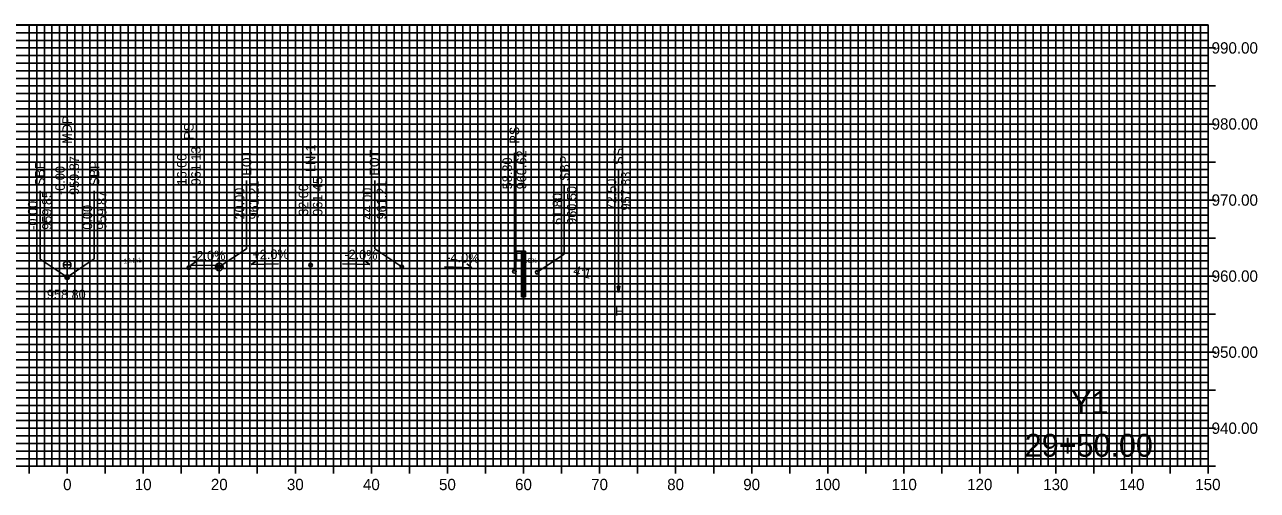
# Model space of a CAD drawing. Extents: x -157 to 156, y 932 to 993.
# Drawn here: x -5.6 to 156.5, y 931.8 to 993.1 of the extents above; entities that cross this region are included whole.
import ezdxf

# ---------------------------------------------------------------- set-up
doc = ezdxf.new("R2010")
doc.units = 0
for name, color, linetype in [('E_NCDOT_Terrain_Model_Boundary', 7, 'Continuous'), ('E_NCDOT_Terrain_Model_Breakline', 7, 'Continuous'), ('E_NCDOT_Terrain_Model_Contour_Imported', 7, 'Continuous'), ('E_NCDOT_Terrain_Model_Contour_Minor', 7, 'Continuous'), ('E_NCDOT_Terrain_Model_Flow_Arrows', 7, 'Continuous'), ('E_NCDOT_Terrain_Model_Hole', 7, 'Continuous'), ('E_NCDOT_Terrain_Model_Island', 7, 'Continuous'), ('E_NCDOT_Terrain_Model_Points_High', 7, 'Continuous'), ('E_NCDOT_Terrain_Model_Points_Low', 7, 'Continuous'), ('E_NCDOT_Terrain_Model_Spot_Elevation', 7, 'Continuous'), ('E_NCDOT_Terrain_Model_Triangles', 7, 'Continuous'), ('E_NCDOT_Terrain_Model_Void', 7, 'Continuous'), ('E_NCDOT_Vertical_Profile_Ground_Line', 7, 'Continuous'), ('P_HYD_Contour_Major', 7, 'Continuous'), ('P_HYD_Contour_Minor', 7, 'Continuous'), ('P_HYD_TC_Ditch_UCE', 7, 'Continuous'), ('P_HYD_TL_Ditch_Boundary', 7, 'Continuous')]:
    doc.layers.add(name, color=color, linetype=linetype)

msp = doc.modelspace()

# ---------------------------------------------------------------- linework, layer by layer
at = {"layer": 'E_NCDOT_Terrain_Model_Boundary'}
for p, q in [((16.2, 961.38), (16.88, 961.87)), ((19.8, 961.45), (16.2, 961.38)), ((24.2, 961.54), (24.88, 962.03)), ((27.8, 961.61), (24.2, 961.54)), ((36.2, 961.61), (39.8, 961.54)), ((39.8, 961.54), (39.12, 962.03)), ((49.6, 961.23), (53.2, 961.09)), ((53.2, 961.09), (52.53, 961.6))]:
    msp.add_line(p, q, dxfattribs=at)
at = {"layer": 'E_NCDOT_Terrain_Model_Breakline'}
for p, q in [((0, 935), (0, 993.06)), ((10, 935), (10, 993.06)), ((20, 935), (20, 993.06)), ((30, 935), (30, 993.06)), ((40, 935), (40, 993.06)), ((50, 935), (50, 993.06)), ((60, 935), (60, 993.06)), ((70, 935), (70, 993.06)), ((80, 935), (80, 993.06)), ((90, 935), (90, 993.06)), ((100, 935), (100, 993.06)), ((110, 935), (110, 993.06)), ((120, 935), (120, 993.06)), ((130, 935), (130, 993.06)), ((140, 935), (140, 993.06)), ((-150, 990), (150, 990)), ((-150, 980), (150, 980)), ((-150, 970), (150, 970)), ((-150, 960), (150, 960)), ((-150, 950), (150, 950)), ((-150, 940), (150, 940))]:
    msp.add_line(p, q, dxfattribs=at)
at = {"layer": 'E_NCDOT_Terrain_Model_Flow_Arrows'}
for p, q in [((-150, 993.06), (150, 993.06)), ((150, 935), (150, 993.06)), ((-150, 935), (150, 935))]:
    msp.add_line(p, q, dxfattribs=at)
at = {"layer": 'E_NCDOT_Terrain_Model_Island'}
for p, q in [((-0.5, 961.47), (0.5, 961.47)), ((0, 961.97), (0, 960.97)), ((19.5, 961.21), (20.5, 961.21)), ((19.5, 961.21), (20.5, 961.21)), ((20, 961.71), (20, 960.71)), ((20, 961.71), (20, 960.71))]:
    msp.add_line(p, q, dxfattribs=at)
for points in [[(-0.5, 961.47), (0, 961.47), (0, 961.97)], [(0.5, 961.47), (0, 961.47), (0, 960.97)], [(19.5, 961.21), (20, 961.21), (20, 961.71)], [(19.5, 961.21), (20, 961.21), (20, 961.71)], [(20.5, 961.21), (20, 961.21), (20, 960.71)], [(20.5, 961.21), (20, 961.21), (20, 960.71)]]:
    msp.add_lwpolyline(points, dxfattribs=at)
for centre in [(0, 961.47), (20, 961.21), (20, 961.21)]:
    msp.add_circle(centre, 0.5, dxfattribs=at)
for centre, start, end in [((0, 961.47), 90, 180), ((0, 961.47), 270, 0), ((20, 961.21), 90, 180), ((20, 961.21), 90, 180), ((20, 961.21), 270, 0), ((20, 961.21), 270, 0)]:
    msp.add_arc(centre, 0.5, start, end, dxfattribs=at)
at = {"layer": 'E_NCDOT_Terrain_Model_Points_High'}
for p, q in [((-150, 993), (150, 993)), ((-150, 992), (150, 992)), ((-4, 935), (-4, 993.06)), ((-3, 935), (-3, 993.06)), ((-2, 935), (-2, 993.06)), ((-1, 935), (-1, 993.06)), ((1, 935), (1, 993.06)), ((2, 935), (2, 993.06)), ((3, 935), (3, 993.06)), ((4, 935), (4, 993.06)), ((6, 935), (6, 993.06)), ((7, 935), (7, 993.06)), ((8, 935), (8, 993.06)), ((9, 935), (9, 993.06)), ((11, 935), (11, 993.06)), ((12, 935), (12, 993.06)), ((13, 935), (13, 993.06)), ((14, 935), (14, 993.06)), ((16, 935), (16, 993.06)), ((17, 935), (17, 993.06)), ((18, 935), (18, 993.06)), ((19, 935), (19, 993.06)), ((21, 935), (21, 993.06)), ((22, 935), (22, 993.06)), ((23, 935), (23, 993.06)), ((24, 935), (24, 993.06)), ((26, 935), (26, 993.06)), ((27, 935), (27, 993.06)), ((28, 935), (28, 993.06)), ((29, 935), (29, 993.06)), ((31, 935), (31, 993.06)), ((32, 935), (32, 993.06)), ((33, 935), (33, 993.06)), ((34, 935), (34, 993.06)), ((36, 935), (36, 993.06)), ((37, 935), (37, 993.06)), ((38, 935), (38, 993.06)), ((39, 935), (39, 993.06)), ((41, 935), (41, 993.06)), ((42, 935), (42, 993.06)), ((43, 935), (43, 993.06)), ((44, 935), (44, 993.06)), ((46, 935), (46, 993.06)), ((47, 935), (47, 993.06)), ((48, 935), (48, 993.06)), ((49, 935), (49, 993.06)), ((51, 935), (51, 993.06)), ((52, 935), (52, 993.06)), ((53, 935), (53, 993.06)), ((54, 935), (54, 993.06)), ((56, 935), (56, 993.06)), ((57, 935), (57, 993.06)), ((58, 935), (58, 993.06)), ((59, 935), (59, 993.06)), ((61, 935), (61, 993.06)), ((62, 935), (62, 993.06)), ((63, 935), (63, 993.06)), ((64, 935), (64, 993.06)), ((66, 935), (66, 993.06)), ((67, 935), (67, 993.06)), ((68, 935), (68, 993.06)), ((69, 935), (69, 993.06)), ((71, 935), (71, 993.06)), ((72, 935), (72, 993.06)), ((73, 935), (73, 993.06)), ((74, 935), (74, 993.06)), ((76, 935), (76, 993.06)), ((77, 935), (77, 993.06)), ((78, 935), (78, 993.06)), ((79, 935), (79, 993.06)), ((81, 935), (81, 993.06)), ((82, 935), (82, 993.06)), ((83, 935), (83, 993.06)), ((84, 935), (84, 993.06)), ((86, 935), (86, 993.06)), ((87, 935), (87, 993.06)), ((88, 935), (88, 993.06)), ((89, 935), (89, 993.06)), ((91, 935), (91, 993.06)), ((92, 935), (92, 993.06)), ((93, 935), (93, 993.06)), ((94, 935), (94, 993.06)), ((96, 935), (96, 993.06)), ((97, 935), (97, 993.06)), ((98, 935), (98, 993.06)), ((99, 935), (99, 993.06)), ((101, 935), (101, 993.06)), ((102, 935), (102, 993.06)), ((103, 935), (103, 993.06)), ((104, 935), (104, 993.06)), ((106, 935), (106, 993.06)), ((107, 935), (107, 993.06)), ((108, 935), (108, 993.06)), ((109, 935), (109, 993.06)), ((111, 935), (111, 993.06)), ((112, 935), (112, 993.06)), ((113, 935), (113, 993.06)), ((114, 935), (114, 993.06)), ((116, 935), (116, 993.06)), ((117, 935), (117, 993.06)), ((118, 935), (118, 993.06)), ((119, 935), (119, 993.06)), ((121, 935), (121, 993.06)), ((122, 935), (122, 993.06)), ((123, 935), (123, 993.06)), ((124, 935), (124, 993.06)), ((126, 935), (126, 993.06)), ((127, 935), (127, 993.06)), ((128, 935), (128, 993.06)), ((129, 935), (129, 993.06)), ((131, 935), (131, 993.06)), ((132, 935), (132, 993.06)), ((133, 935), (133, 993.06)), ((134, 935), (134, 993.06)), ((136, 935), (136, 993.06)), ((137, 935), (137, 993.06)), ((138, 935), (138, 993.06)), ((139, 935), (139, 993.06)), ((141, 935), (141, 993.06)), ((142, 935), (142, 993.06)), ((143, 935), (143, 993.06)), ((144, 935), (144, 993.06)), ((146, 935), (146, 993.06)), ((147, 935), (147, 993.06)), ((148, 935), (148, 993.06)), ((149, 935), (149, 993.06)), ((-150, 991), (150, 991)), ((-150, 989), (150, 989)), ((-150, 988), (150, 988)), ((-150, 987), (150, 987)), ((-150, 986), (150, 986)), ((-150, 984), (150, 984)), ((-150, 983), (150, 983)), ((-150, 982), (150, 982)), ((-150, 981), (150, 981)), ((-150, 979), (150, 979)), ((-150, 978), (150, 978)), ((-150, 977), (150, 977)), ((-150, 976), (150, 976)), ((-150, 974), (150, 974)), ((-150, 973), (150, 973)), ((-150, 972), (150, 972)), ((-150, 971), (150, 971)), ((-150, 969), (150, 969)), ((-150, 968), (150, 968)), ((-150, 967), (150, 967)), ((-150, 966), (150, 966)), ((-150, 964), (150, 964)), ((-150, 963), (150, 963)), ((-150, 962), (150, 962)), ((-150, 961), (150, 961)), ((-150, 959), (150, 959)), ((-150, 958), (150, 958)), ((-150, 957), (150, 957)), ((-150, 956), (150, 956)), ((-150, 954), (150, 954)), ((-150, 953), (150, 953)), ((-150, 952), (150, 952)), ((-150, 951), (150, 951)), ((-150, 949), (150, 949)), ((-150, 948), (150, 948)), ((-150, 947), (150, 947)), ((-150, 946), (150, 946)), ((-150, 944), (150, 944)), ((-150, 943), (150, 943)), ((-150, 942), (150, 942)), ((-150, 941), (150, 941)), ((-150, 939), (150, 939)), ((-150, 938), (150, 938)), ((-150, 937), (150, 937)), ((-150, 936), (150, 936))]:
    msp.add_line(p, q, dxfattribs=at)
at = {"layer": 'E_NCDOT_Terrain_Model_Points_Low'}
for p, q in [((-5, 935), (-5, 993.06)), ((0, 935), (0, 993.06)), ((5, 935), (5, 993.06)), ((10, 935), (10, 993.06)), ((15, 935), (15, 993.06)), ((20, 935), (20, 993.06)), ((25, 935), (25, 993.06)), ((30, 935), (30, 993.06)), ((35, 935), (35, 993.06)), ((40, 935), (40, 993.06)), ((45, 935), (45, 993.06)), ((50, 935), (50, 993.06)), ((55, 935), (55, 993.06)), ((60, 935), (60, 993.06)), ((65, 935), (65, 993.06)), ((70, 935), (70, 993.06)), ((75, 935), (75, 993.06)), ((80, 935), (80, 993.06)), ((85, 935), (85, 993.06)), ((90, 935), (90, 993.06)), ((95, 935), (95, 993.06)), ((100, 935), (100, 993.06)), ((105, 935), (105, 993.06)), ((110, 935), (110, 993.06)), ((115, 935), (115, 993.06)), ((120, 935), (120, 993.06)), ((125, 935), (125, 993.06)), ((130, 935), (130, 993.06)), ((135, 935), (135, 993.06)), ((140, 935), (140, 993.06)), ((145, 935), (145, 993.06)), ((-150, 990), (150, 990)), ((150.96, 990), (150, 990)), ((-150, 985), (150, 985)), ((150.96, 985), (150, 985)), ((-150, 980), (150, 980)), ((150.96, 980), (150, 980)), ((-150, 975), (150, 975)), ((150.96, 975), (150, 975)), ((-150, 970), (150, 970)), ((150.96, 970), (150, 970)), ((-150, 965), (150, 965)), ((150.96, 965), (150, 965)), ((-150, 960), (150, 960)), ((150.96, 960), (150, 960)), ((-150, 955), (150, 955)), ((150.96, 955), (150, 955)), ((-150, 950), (150, 950)), ((150.96, 950), (150, 950)), ((-150, 945), (150, 945)), ((150.96, 945), (150, 945)), ((-150, 940), (150, 940)), ((150.96, 940), (150, 940)), ((-5, 935), (-5, 934.04)), ((0, 935), (0, 934.04)), ((5, 935), (5, 934.04)), ((10, 935), (10, 934.04)), ((15, 935), (15, 934.04)), ((20, 935), (20, 934.04)), ((25, 935), (25, 934.04)), ((30, 935), (30, 934.04)), ((35, 935), (35, 934.04)), ((40, 935), (40, 934.04)), ((45, 935), (45, 934.04)), ((50, 935), (50, 934.04)), ((55, 935), (55, 934.04)), ((60, 935), (60, 934.04)), ((65, 935), (65, 934.04)), ((70, 935), (70, 934.04)), ((75, 935), (75, 934.04)), ((80, 935), (80, 934.04)), ((85, 935), (85, 934.04)), ((90, 935), (90, 934.04)), ((95, 935), (95, 934.04)), ((100, 935), (100, 934.04)), ((105, 935), (105, 934.04)), ((110, 935), (110, 934.04)), ((115, 935), (115, 934.04)), ((120, 935), (120, 934.04)), ((125, 935), (125, 934.04)), ((130, 935), (130, 934.04)), ((135, 935), (135, 934.04)), ((140, 935), (140, 934.04)), ((145, 935), (145, 934.04)), ((150, 935), (150, 934.04)), ((150.96, 935), (150, 935))]:
    msp.add_line(p, q, dxfattribs=at)
at = {"layer": 'E_NCDOT_Terrain_Model_Triangles'}
for p, q in [((23.56, 963.61), (23.56, 972.56)), ((40.44, 963.61), (40.44, 972.56)), ((-3.56, 962.25), (-3.56, 971.2)), ((3.56, 962.26), (3.56, 971.22)), ((65.36, 962.9), (65.36, 971.85)), ((20, 961.21), (23.56, 963.61)), ((44, 961.21), (40.44, 963.61)), ((61.8, 960.5), (65.36, 962.9)), ((0, 959.85), (-3.56, 962.25)), ((0, 959.87), (3.56, 962.26))]:
    msp.add_line(p, q, dxfattribs=at)
at = {"layer": 'E_NCDOT_Terrain_Model_Void'}
for p, q in [((58.97, 963.19), (58.84, 963.09)), ((58.84, 962.96), (59.05, 962.82)), ((59.07, 963.21), (58.99, 963.19)), ((59.75, 963.29), (59.08, 963.29)), ((59.08, 963.29), (59.08, 962.12)), ((59.08, 962.75), (59.08, 962.71)), ((59.08, 962.71), (59.08, 962.66)), ((59.75, 963.29), (60.25, 963.29)), ((59.76, 963.29), (59.75, 963.29)), ((59.75, 963.29), (59.75, 957.29)), ((59.76, 957.29), (59.76, 963.29)), ((60.25, 963.29), (60.23, 963.29)), ((60.23, 963.29), (60.23, 957.29)), ((60.25, 957.29), (60.25, 963.29)), ((59.05, 962.59), (58.84, 962.45)), ((58.84, 962.32), (58.97, 962.22)), ((58.99, 962.22), (59.07, 962.2)), ((59.08, 962.12), (59.75, 962.12)), ((59.75, 957.29), (60.25, 957.29)), ((59.75, 957.29), (59.76, 957.29)), ((60.23, 957.29), (60.25, 957.29))]:
    msp.add_line(p, q, dxfattribs=at)
for centre, radius, start, end in [((58.88, 963.03), 0.0787, 125.2976, 235.3478), ((58.99, 963.16), 0.0328, 100, 125.2976), ((59, 962.75), 0.0787, 0.02, 55.3478), ((58.88, 962.38), 0.0787, 124.6522, 234.7024), ((58.99, 962.25), 0.0328, 234.7024, 260), ((59, 962.66), 0.0787, 304.6522, 359.98)]:
    msp.add_arc(centre, radius, start, end, dxfattribs=at)
at = {"layer": 'E_NCDOT_Vertical_Profile_Ground_Line'}
for p, q in [((0, 959.87), (0, 976.07)), ((16, 961.13), (16, 976.73)), ((58.8, 960.62), (58.8, 976.22)), ((32, 961.45), (32, 973.57)), ((72.5, 957.83), (72.5, 974.03))]:
    msp.add_line(p, q, dxfattribs=at)
msp.add_lwpolyline([(72.5, 957.83), (72.32, 958.65), (72.67, 958.65)], close=True, dxfattribs=at)
for centre, radius in [((16, 961.13), 0.24), ((20, 961.21), 0.24), ((32, 961.45), 0.24), ((44, 961.21), 0.24), ((0, 959.87), 0.3), ((0, 959.87), 0.24), ((0, 959.85), 0.24), ((58.8, 960.62), 0.24), ((61.8, 960.5), 0.24)]:
    msp.add_circle(centre, radius, dxfattribs=at)

# ---------------------------------------------------------------- texts
at = {"layer": 'E_NCDOT_Terrain_Model_Contour_Imported'}
msp.add_text('958.80', height=1.248, dxfattribs=at).set_placement((-2.67, 956.97))
at = {"layer": 'E_NCDOT_Terrain_Model_Contour_Minor'}
for s, p in [('SS', (73.12, 974.63)), ('72.50', (72.19, 968.63)), ('957.83', (74.06, 968.63))]:
    msp.add_text(s, height=1.248, rotation=90, dxfattribs=at).set_placement(p)
msp.add_text('F', height=1.25, dxfattribs=at).set_placement((72.02, 954.81))
at = {"layer": 'E_NCDOT_Terrain_Model_Hole'}
for s, height, p in [('990.00', 1.488, (150.47, 989.26)), ('980.00', 1.488, (150.47, 979.26)), ('970.00', 1.488, (150.47, 969.26)), ('960.00', 1.488, (150.47, 959.26)), ('950.00', 1.488, (150.47, 949.26)), ('940.00', 1.488, (150.47, 939.26)), ('0', 1.49, (-0.53, 931.86)), ('10', 1.488, (8.89, 931.86)), ('20', 1.488, (18.89, 931.86)), ('30', 1.488, (28.89, 931.86)), ('40', 1.488, (38.89, 931.86)), ('50', 1.488, (48.89, 931.86)), ('60', 1.488, (58.89, 931.86)), ('70', 1.488, (68.89, 931.86)), ('80', 1.488, (78.89, 931.86)), ('90', 1.488, (88.89, 931.86)), ('100', 1.488, (98.32, 931.86)), ('110', 1.488, (108.39, 931.86)), ('120', 1.488, (118.32, 931.86)), ('130', 1.488, (128.32, 931.86)), ('140', 1.488, (138.32, 931.86)), ('150', 1.488, (148.32, 931.86))]:
    msp.add_text(s, height=height, dxfattribs=at).set_placement(p)
at = {"layer": 'E_NCDOT_Terrain_Model_Spot_Elevation'}
msp.add_text('12.5:1', height=0.624, rotation=4.5739, dxfattribs=at).set_placement((7.43, 961.65))
at = {"layer": 'P_HYD_Contour_Major'}
for s, rotation, p in [('+2.0%', 1.1458, (24.36, 962.19)), ('-2.0%', 358.8542, (36.43, 962.25))]:
    msp.add_text(s, height=1.248, rotation=rotation, dxfattribs=at).set_placement(p)
at = {"layer": 'P_HYD_Contour_Minor'}
for s, height, rotation, p in [('-2.0%', 1.248, 1.1458, (16.45, 962.03)), ('-4.0%', 1.248, 357.7094, (49.83, 961.87)), ('-4.0%', 0.624, 357.7094, (59.52, 961.79)), ('4:1', 1.248, 345.9638, (66.46, 960.21))]:
    msp.add_text(s, height=height, rotation=rotation, dxfattribs=at).set_placement(p)
at = {"layer": 'P_HYD_TC_Ditch_UCE'}
for s, p in [('Y1', (132, 941.9)), ('29+50.00', (125.9, 936.26))]:
    msp.add_text(s, height=3, dxfattribs=at).set_placement(p)
at = {"layer": 'P_HYD_TL_Ditch_Boundary'}
for s, p in [('MDP', (0.62, 977.39)), ('PS', (16.62, 977.93)), ('PS', (59.43, 977.42)), ('959.87', (1.56, 970.67)), ('16.00', (15.69, 971.93)), ('961.13', (17.56, 971.93)), ('EOT', (24.22, 973.21)), ('LN-1', (32.62, 973.69)), ('EOT', (41.02, 973.21)), ('960.62', (60.36, 971.42)), ('SBP', (66.03, 972.5)), ('SBP', (-2.98, 971.85)), ('-0.00', (-0.31, 970.67)), ('SBP', (4.22, 971.87)), ('58.80', (58.49, 971.42)), ('961.21', (25.16, 967.45)), ('961.45', (33.56, 967.93)), ('961.21', (41.96, 967.45)), ('959.85', (-2.04, 966.09)), ('959.87', (5.16, 966.11)), ('20.00', (23.29, 967.45)), ('32.00', (31.69, 967.93)), ('44.00', (40.09, 967.45)), ('61.80', (65.09, 966.74)), ('960.50', (66.96, 966.74)), ('-0.00', (-3.91, 966.09)), ('0.00', (3.29, 966.11))]:
    msp.add_text(s, height=1.248, rotation=90, dxfattribs=at).set_placement(p)

doc.saveas('drawing.dxf')
